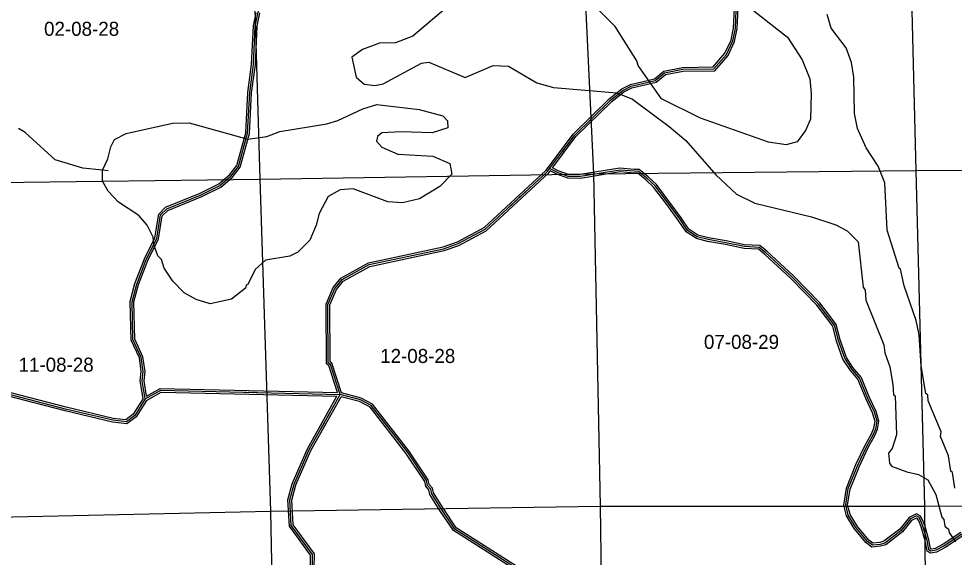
# Model space of a CAD drawing. Extents: x 418523 to 616617, y 1878279 to 2196743.
# Drawn here: x 511589 to 526595, y 1991620 to 2000254 of the extents above; entities that cross this region are included whole.
import ezdxf

# ---------------------------------------------------------------- set-up
doc = ezdxf.new("R2010")
doc.units = 0
for name, color, linetype in [('Level 1', 7, 'Continuous'), ('Level 2', 7, 'Continuous'), ('Level 31', 7, 'Continuous'), ('Level 32', 7, 'Continuous'), ('Level 34', 7, 'Continuous'), ('Level 5', 7, 'Continuous'), ('Level 7', 7, 'Continuous')]:
    doc.layers.add(name, color=color, linetype=linetype)

msp = doc.modelspace()

# ---------------------------------------------------------------- linework, layer by layer
at = {"layer": 'Level 1'}
for p, q in [((515299.141, 2003029.736), (515453.977, 1997681.434)), ((520557.166, 2003082.783), (520810.216, 1997767.897)), ((525842.86, 2003085.605), (525980.237, 1997819.496)), ((515453.977, 1997681.434), (520810.216, 1997767.897)), ((520810.216, 1997767.897), (525980.237, 1997819.496)), ((520810.216, 1997767.897), (520915.189, 1992439.929)), ((525980.237, 1997819.496), (531292.1, 1997848.181)), ((525980.237, 1997819.496), (526116.865, 1992439.277)), ((510207.858, 1997614.298), (515453.977, 1997681.434)), ((515453.977, 1997681.434), (515628.969, 1992357.029)), ((510332.552, 1992244.161), (515628.969, 1992357.029)), ((515628.969, 1992357.029), (520915.189, 1992439.929)), ((515628.969, 1992357.029), (515730.06, 1987047.101)), ((520915.189, 1992439.929), (520996.349, 1987140.138)), ((520915.189, 1992439.929), (526116.865, 1992439.277)), ((526116.865, 1992439.277), (531388.797, 1992478.224)), ((526116.865, 1992439.277), (526172.277, 1987177.686))]:
    msp.add_line(p, q, dxfattribs=at)
at = {"layer": 'Level 31'}
for points in [[(520103.823, 1997850.831), (520502.17, 1998383.211), (521079.467, 1998948.029), (521280.132, 1999105.483), (521413.872, 1999171.905), (521797.566, 1999262.138), (521948.004, 1999386.323), (522240.254, 1999443.803), (522740.326, 1999450.342), (522941.252, 1999682.719), (523042.238, 1999899.095), (523084.501, 2000098.956), (523102.879, 2000532.376), (522938.127, 2001091.561), (522856.783, 2001567.166)], [(513617.072, 1994157.765), (513568.099, 1994449.614), (513585.174, 1994599.74), (513552.75, 1994824.974), (513420.342, 1995108.784), (513406.22, 1995717.249), (513482.164, 1996000.611), (513633.681, 1996391.688), (513801.81, 1996732.878), (513861.614, 1997107.947), (513961.889, 1997207.566), (514512.935, 1997430.538), (514813.81, 1997579.57), (514989.428, 1997728.721), (515114.975, 1997886.796), (515258.768, 1998419.738), (515294.561, 1999069.831), (515354.634, 1999519.817), (515381.735, 2000136.488), (515432.761, 2000378.128)], [(516743.352, 1994229.377), (516586.942, 1994713.282), (516553.74, 1994738.501), (516548.73, 1995672.045), (516658.168, 1995930.193), (516775.405, 1996071.576), (517209.815, 1996311.397), (518402.81, 1996565.457), (518636.515, 1996647.858), (519070.877, 1996879.701), (520066.539, 1997801.512), (520103.823, 1997850.831)], [(523465.933, 1996587.861), (523228.463, 1996601.087), (522929.018, 1996663.634), (522644.426, 1996711.946), (522471.133, 1996757.672), (522318.023, 1996859.692), (522190.9, 1997043.807), (521993.056, 1997312.915), (521795.193, 1997575.841), (521665.302, 1997695.599), (521529.987, 1997806.286), (521459.6, 1997808.727), (521233.575, 1997827.741), (520598.035, 1997723.899), (520401.436, 1997725.718), (520231.07, 1997789.264), (520103.823, 1997850.831)], [(526716.938, 1991991.546), (526430.831, 1991801.999), (526299.285, 1991733.37), (526219.944, 1991718.377), (526187.665, 1991738.493), (526157.441, 1991890.975), (526091.65, 1992119.951), (526052.983, 1992216.459), (526026.498, 1992260.556), (525988.205, 1992283.602), (525891.622, 1992235.942), (525743.169, 1992049.911), (525480.485, 1991848.651), (525404.292, 1991827.467), (525281.192, 1991815.177), (525201.794, 1991873.284), (525015.795, 1992098.327), (524894.391, 1992294.412), (524852.481, 1992458.573), (524894.964, 1992720.258), (525045.359, 1993094.291), (525193.3, 1993403.602), (525289.051, 1993574.545), (525335.415, 1993680.569), (525355.189, 1993800.871), (525313.215, 1993947.576), (525209.661, 1994167.234), (525075.725, 1994492.463), (524945.936, 1994647.12), (524836.478, 1994810.796), (524735.064, 1995095.181), (524672.194, 1995338.696), (524568.997, 1995478.713), (524415.282, 1995680.371), (523993.472, 1996109.556), (523569.007, 1996503.482), (523465.933, 1996587.861)], [(513617.072, 1994157.765), (513449.223, 1993891.488), (513315.637, 1993792.001), (513098.815, 1993817.94), (512340.915, 1993995.83), (510575.32, 1994452.656)], [(513617.072, 1994157.765), (513867.52, 1994298.256), (516743.352, 1994229.377)], [(515696.484, 1990748.391), (516249.015, 1991338.321), (516299.57, 1991454.864), (516300.364, 1991663.241), (515960.258, 1992131.483), (515936.764, 1992539.966), (516004.32, 1992789.908), (516248.113, 1993347.564), (516743.352, 1994229.377)], [(525444.75, 1989294.421), (525128.43, 1989445.741), (524986.715, 1989462.976), (524286.57, 1989424.031), (523302.916, 1989486.131), (523094.715, 1989536.707), (522911.784, 1989645.743), (522803.858, 1989796.328), (522822.061, 1990179.925), (522705.678, 1990271.991), (521631.744, 1990617.758), (520873.218, 1990654.006), (520481.977, 1990863.831), (518586.059, 1992071.346), (518370.319, 1992388.907), (518213.004, 1992639.699), (518196.476, 1992714.676), (518146.905, 1992773.412), (518130.378, 1992848.39), (517823.528, 1993308.126), (517242.802, 1994052.196), (517068.094, 1994144.501), (516743.352, 1994229.377)]]:
    msp.add_lwpolyline(points, dxfattribs=at)
at = {"layer": 'Level 32'}
for points in [[(520079.891, 1997868.923), (520479.535, 1998403.038), (521059.658, 1998970.62), (521264.032, 1999130.984), (521403.63, 1999200.316), (521783.874, 1999289.737), (521934.762, 1999414.295), (522237.137, 1999473.766), (522726.451, 1999480.165), (522915.83, 1999699.186), (523013.598, 1999908.666), (523054.633, 2000102.721), (523072.695, 2000528.673), (522908.852, 2001084.771), (522831.631, 2001536.276)], [(520149.643, 1997861.99), (520524.805, 1998363.386), (521099.276, 1998925.439), (521296.232, 1999079.981), (521424.114, 1999143.494), (521811.259, 1999234.54), (521961.245, 1999358.352), (522243.37, 1999413.841), (522754.201, 1999420.52), (522966.675, 1999666.251), (523070.878, 1999889.524), (523114.37, 2000095.191), (523133.064, 2000536.079), (522967.402, 2001098.353), (522886.127, 2001573.554)], [(513585.593, 1994164.083), (513537.814, 1994448.811), (513554.929, 1994599.291), (513523.688, 1994816.31), (513390.496, 1995101.8), (513376.128, 1995720.857), (513453.605, 1996009.941), (513606.185, 1996403.761), (513772.896, 1996742.076), (513833.527, 1997122.334), (513945.033, 1997233.109), (514500.634, 1997457.924), (514797.195, 1997604.82), (514967.765, 1997749.683), (515087.625, 1997900.598), (515228.985, 1998424.521), (515264.67, 1999072.646), (515324.72, 1999522.466), (515351.871, 2000140.271), (515395.969, 2000349.095)], [(513639.6, 1994204.799), (513598.385, 1994450.416), (513615.419, 1994600.19), (513581.814, 1994833.639), (513450.189, 1995115.767), (513436.312, 1995713.641), (513510.723, 1995991.281), (513661.177, 1996379.615), (513830.723, 1996723.681), (513889.7, 1997093.561), (513978.745, 1997182.023), (514525.238, 1997403.153), (514830.425, 1997554.321), (515011.091, 1997707.76), (515142.324, 1997872.993), (515288.55, 1998414.954), (515324.453, 1999067.017), (515384.547, 1999517.168), (515411.598, 2000132.705), (515456.952, 2000347.472)], [(516701.802, 1994260.381), (516561.294, 1994695.091), (516523.818, 1994723.556), (516518.697, 1995678.064), (516632.265, 1995945.955), (516755.935, 1996095.096), (517199.213, 1996339.813), (518394.664, 1996594.396), (518624.395, 1996675.395), (519053.335, 1996904.345), (520044.209, 1997821.722), (520079.891, 1997868.923)], [(516766.844, 1994254.246), (516612.59, 1994731.474), (516583.66, 1994753.448), (516578.764, 1995666.025), (516684.071, 1995914.431), (516794.875, 1996048.055), (517220.417, 1996282.982), (518410.957, 1996536.518), (518648.636, 1996620.321), (519088.419, 1996855.058), (520088.869, 1997781.302), (520112.913, 1997813.105)], [(523454.499, 1996558.45), (523224.54, 1996571.258), (522923.439, 1996634.151), (522638.075, 1996682.594), (522458.652, 1996729.938), (522296.602, 1996837.916), (522166.465, 1997026.396), (521968.985, 1997295.009), (521772.857, 1997555.628), (521645.62, 1997672.94), (521518.83, 1997776.655), (521457.822, 1997778.77), (521234.754, 1997797.536), (520600.331, 1997693.876), (520395.889, 1997695.767), (520219.269, 1997761.646), (520112.913, 1997813.106)], [(523477.369, 1996617.271), (523232.385, 1996630.916), (522934.598, 1996693.116), (522650.777, 1996741.297), (522483.614, 1996785.406), (522339.444, 1996881.47), (522215.335, 1997061.219), (522017.128, 1997330.821), (521817.529, 1997596.053), (521684.985, 1997718.258), (521541.145, 1997835.918), (521461.378, 1997838.685), (521232.396, 1997857.947), (520595.737, 1997753.921), (520406.984, 1997755.669), (520242.872, 1997816.881), (520149.642, 1997861.989)], [(526733.609, 1991966.604), (526446.096, 1991776.125), (526309.223, 1991704.716), (526214.012, 1991686.725), (526160.765, 1991719.908), (526128.258, 1991883.903), (526063.237, 1992110.205), (526026.028, 1992203.071), (526004.626, 1992238.704), (525986.781, 1992249.445), (525910.898, 1992211.999), (525764.329, 1992028.33), (525494.119, 1991821.303), (525409.841, 1991797.871), (525272.744, 1991784.184), (525181.055, 1991851.285), (524991.365, 1992080.794), (524866.462, 1992282.533), (524821.866, 1992457.21), (524865.885, 1992728.356), (525017.881, 1993106.372), (525166.654, 1993417.42), (525262.155, 1993587.918), (525306.421, 1993689.145), (525324.493, 1993799.092), (525285.041, 1993936.985), (525182.206, 1994155.118), (525049.755, 1994476.74), (524921.905, 1994629.085), (524809.471, 1994797.213), (524706.354, 1995086.375), (524644.598, 1995325.572), (524544.99, 1995460.719), (524392.565, 1995660.686), (523972.559, 1996088.036), (523549.282, 1996480.858), (523454.499, 1996558.45)], [(526700.267, 1992016.49), (526415.566, 1991827.874), (526289.348, 1991762.023), (526225.876, 1991750.03), (526214.565, 1991757.078), (526186.625, 1991898.046), (526120.065, 1992129.697), (526079.939, 1992229.846), (526048.37, 1992282.407), (525989.63, 1992317.76), (525872.346, 1992259.885), (525722.009, 1992071.493), (525466.851, 1991875.999), (525398.743, 1991857.062), (525289.641, 1991846.171), (525222.533, 1991895.283), (525040.224, 1992115.861), (524922.321, 1992306.292), (524883.096, 1992459.937), (524924.042, 1992712.159), (525072.836, 1993082.211), (525219.947, 1993389.785), (525315.947, 1993561.171), (525364.408, 1993671.993), (525385.885, 1993802.648), (525341.389, 1993958.167), (525237.117, 1994179.35), (525101.694, 1994508.186), (524969.966, 1994665.155), (524863.485, 1994824.38), (524763.775, 1995103.986), (524699.79, 1995351.821), (524593.003, 1995496.706), (524438, 1995700.056), (524014.385, 1996131.077), (523588.732, 1996526.106), (523477.369, 1996617.271)], [(513585.592, 1994164.082), (513426.823, 1993912.213), (513307.316, 1993823.211), (513104.04, 1993847.529), (512348.1, 1994024.959), (510614.295, 1994473.56)], [(513638.392, 1994135.324), (513471.623, 1993870.764), (513323.958, 1993760.791), (513093.59, 1993788.351), (512333.73, 1993966.701), (510568.488, 1994423.433)], [(513639.6, 1994204.799), (513860.016, 1994328.445), (516701.802, 1994260.381)], [(513638.392, 1994135.324), (513875.025, 1994268.067), (516692.771, 1994200.579)], [(515666.339, 1990760.09), (516223.561, 1991355.033), (516269.594, 1991461.146), (516270.326, 1991653.546), (515930.812, 1992120.973), (515906.533, 1992543.099), (515975.939, 1992799.886), (516221.223, 1993360.951), (516692.771, 1994200.579)], [(515726.63, 1990736.691), (516274.467, 1991321.61), (516329.547, 1991448.583), (516330.402, 1991672.935), (515989.703, 1992141.993), (515966.995, 1992536.833), (516032.7, 1992779.931), (516275.003, 1993334.176), (516758.171, 1994194.496)], [(525421.045, 1989272.502), (525119.923, 1989416.554), (524985.73, 1989432.875), (524286.458, 1989393.977), (523298.395, 1989456.356), (523083.24, 1989508.621), (522891.046, 1989623.178), (522773.396, 1989787.33), (522791.365, 1990165.956), (522691.32, 1990245.096), (521626.338, 1990587.981), (520865.014, 1990624.364), (520466.808, 1990837.923), (518564.721, 1992049.367), (518345.195, 1992372.501), (518184.825, 1992628.163), (518168.773, 1992700.986), (518119.202, 1992759.722), (518102.294, 1992836.425), (517799.192, 1993290.545), (517223.105, 1994028.671), (517057.149, 1994116.354), (516758.171, 1994194.496)], [(525435.758, 1989331.979), (525136.937, 1989474.929), (524987.7, 1989493.078), (524286.681, 1989454.084), (523307.436, 1989515.906), (523106.19, 1989564.793), (522932.521, 1989668.308), (522834.32, 1989805.326), (522852.759, 1990193.894), (522720.036, 1990298.885), (521637.15, 1990647.535), (520881.421, 1990683.649), (520497.146, 1990889.738), (518607.396, 1992093.326), (518395.443, 1992405.313), (518241.181, 1992651.236), (518224.179, 1992728.366), (518174.608, 1992787.102), (518158.461, 1992860.355), (517847.863, 1993325.706), (517262.5, 1994075.72), (517079.038, 1994172.649), (516766.843, 1994254.245)]]:
    msp.add_lwpolyline(points, dxfattribs=at)
at = {"layer": 'Level 5'}
msp.add_line((513025.697, 1997815.229), (512934.025, 1997823.858), dxfattribs=at)
msp.add_lwpolyline([(512934.025, 1997823.858), (512617.347, 1997858.255), (512175.974, 1997993.043), (511693.875, 1998428.097), (511585.691, 1998495.148)], dxfattribs=at)
at = {"layer": 'Level 7'}
for points in [[(518436.11, 2000415.36), (517909.485, 1999975.233), (517634.031, 1999867.776), (517375.595, 1999860.253), (517100.17, 1999761.097), (516933.018, 1999636.612), (516998.695, 1999319.606), (517131.69, 1999202.465), (517298.385, 1999185.276), (517431.828, 1999209.818)], [(523379.508, 2000382.701), (523919.969, 1999955.807), (524152.24, 1999596.591), (524276.279, 1999287.726), (524300.533, 1999054.241), (524290.89, 1998645.791), (524206.941, 1998462.655), (524072.971, 1998279.679), (523897.748, 1998230.216), (523614.44, 1998272.813), (522523.618, 1998659.849), (521899.368, 1998970.288), (521525.96, 1999505.026), (521501.218, 1999580.148), (521152.85, 2000131.467), (520862.028, 2000424.181)], [(526605.978, 1992727.757), (526565.113, 1992977.983), (526540.162, 1993003.093), (526499.266, 1993244.978), (526375.198, 1993553.814), (526383.797, 1993628.806), (526176.994, 1994129.676), (526168.952, 1994221.407), (526135.7, 1994246.518), (526062.111, 1994688.567), (526030.361, 1995188.879), (525981.066, 1995414.124), (525791.152, 1995973.285), (525733.646, 1996240.211), (525708.705, 1996256.981), (525518.93, 1996866.163), (525479.696, 1997624.901), (525372.199, 1997891.986), (525181.38, 1998184.381), (525040.67, 1998493.286), (524991.445, 1998735.201), (524984.995, 1999318.786), (524944.07, 1999552.331), (524861.454, 1999786.016), (524620.712, 2000103.58), (524554.737, 2000320.554)], [(517431.828, 1999209.818), (518049.796, 1999541.284), (518166.569, 1999557.596), (518749.337, 1999313.947), (519200.115, 1999504.247), (519441.84, 1999495.121), (519899.455, 1999226.86), (520165.994, 1999150.981), (521182.769, 1999064.311), (521432.537, 1998963.492), (522023.008, 1998528.069), (522289.029, 1998302.137), (522770.77, 1997750.37), (523103.213, 1997440.846), (523394.532, 1997298.176), (524302.508, 1997078.493), (524693.889, 1996952.175), (524876.965, 1996851.545), (525051.472, 1996675.922), (525132.487, 1995950.406), (525165.669, 1995900.256), (525173.511, 1995741.861), (525462.971, 1995023.988), (525479.214, 1994898.876), (525561.86, 1994673.531), (525610.965, 1994389.935), (525618.779, 1994223.171), (525643.72, 1994206.431), (525666.711, 1993581.106), (525599.333, 1993364.59), (525540.713, 1993289.757), (525556.866, 1993131.304), (525590.088, 1993081.193), (525831.515, 1992988.704), (526023.12, 1992946.405), (526172.905, 1992862.545), (526297.202, 1992628.741), (526396.061, 1992261.613), (526429.283, 1992228.163), (526445.625, 1992119.731), (526503.817, 1992069.51), (526511.988, 1992019.459), (526611.533, 1991869.086)]]:
    msp.add_lwpolyline(points, dxfattribs=at)
msp.add_lwpolyline([(512934.025, 1997823.858), (513017.984, 1998007.004), (513068.621, 1998198.569), (513127.361, 1998315.082), (513311.094, 1998414.537), (514053.549, 1998578.871), (514320.345, 1998586.324), (515261.501, 1998324.86), (515570.078, 1998365.565), (515778.751, 1998448.239), (516529.447, 1998570.861), (516704.67, 1998620.295), (517105.437, 1998810.755), (517330.721, 1998876.699), (518014.069, 1998799.476), (518388.879, 1998698.228), (518463.642, 1998614.606), (518471.625, 1998506.204), (518221.27, 1998423.659), (517721.128, 1998441.963), (517412.64, 1998426.269), (517345.76, 1998368.146), (517328.821, 1998293.155), (517411.895, 1998192.853), (517669.963, 1998083.664), (518228.366, 1998048.49), (518503.105, 1997930.891), (518535.899, 1997764.067), (518343.548, 1997564.62), (518017.774, 1997365.591), (517742.448, 1997299.786), (517509.092, 1997317.203), (516951.235, 1997527.451), (516742.77, 1997511.428), (516550.668, 1997403.673), (516408.07, 1997129.035), (516357.461, 1996945.8), (516256.643, 1996704.372), (516064.292, 1996513.256), (515939.01, 1996446.992), (515547.012, 1996381.536), (515379.79, 1996232.04), (515262.302, 1995990.642), (515237.261, 1995982.412), (515228.762, 1995932.421), (515003.12, 1995758.074), (514661.103, 1995684.157), (514436.216, 1995751.576), (514244.84, 1995860.566), (514062.032, 1996044.559), (513920.995, 1996253.422), (513879.772, 1996395.275), (513821.61, 1996453.826), (513755.475, 1996629.109), (513747.533, 1996754.192), (513648.117, 1996946.226), (513515.221, 1997096.737), (513190.82, 1997314.529), (513024.653, 1997490.111), (512933.478, 1997648.794), (512934.025, 1997823.858)], close=True, dxfattribs=at)

# ---------------------------------------------------------------- texts
at = {"layer": 'Level 2'}
for s, p in [('02-08-28', (511995.135, 1999979.732)), ('07-08-29', (522579.49, 1994960.29)), ('12-08-28', (517386.326, 1994734.663)), ('11-08-28', (511586.69, 1994595.247))]:
    msp.add_text(s, height=225, dxfattribs=at).set_placement(p)
at = {"layer": 'Level 34'}
for s, height, rotation, p in [('MOODY SHANTY ROAD', 25, 53.3861055, (520298.837, 1998090.962)), ('MOODY SHANTY ROAD', 25, 42.7934777, (519451.006, 1997214.606)), ('TRIAY ROAD', 24.9992, 358.6272667, (515213.989, 1994253.506)), ('MESSERVEY ROAD', 25, 60.6798861, (516438.845, 1993661.659))]:
    msp.add_text(s, height=height, rotation=rotation, dxfattribs=at).set_placement(p)

doc.saveas('drawing.dxf')
